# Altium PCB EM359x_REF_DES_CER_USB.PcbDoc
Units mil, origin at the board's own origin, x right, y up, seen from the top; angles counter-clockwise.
Board outline 2000 x 1729.04 mil, 4 copper layers (Top Layer, Gnd Layer 2, Power Layer 3, Bottom Layer), stack 61.6 mil thick; 70 components, 61 nets, 290 pads, 313 vias.
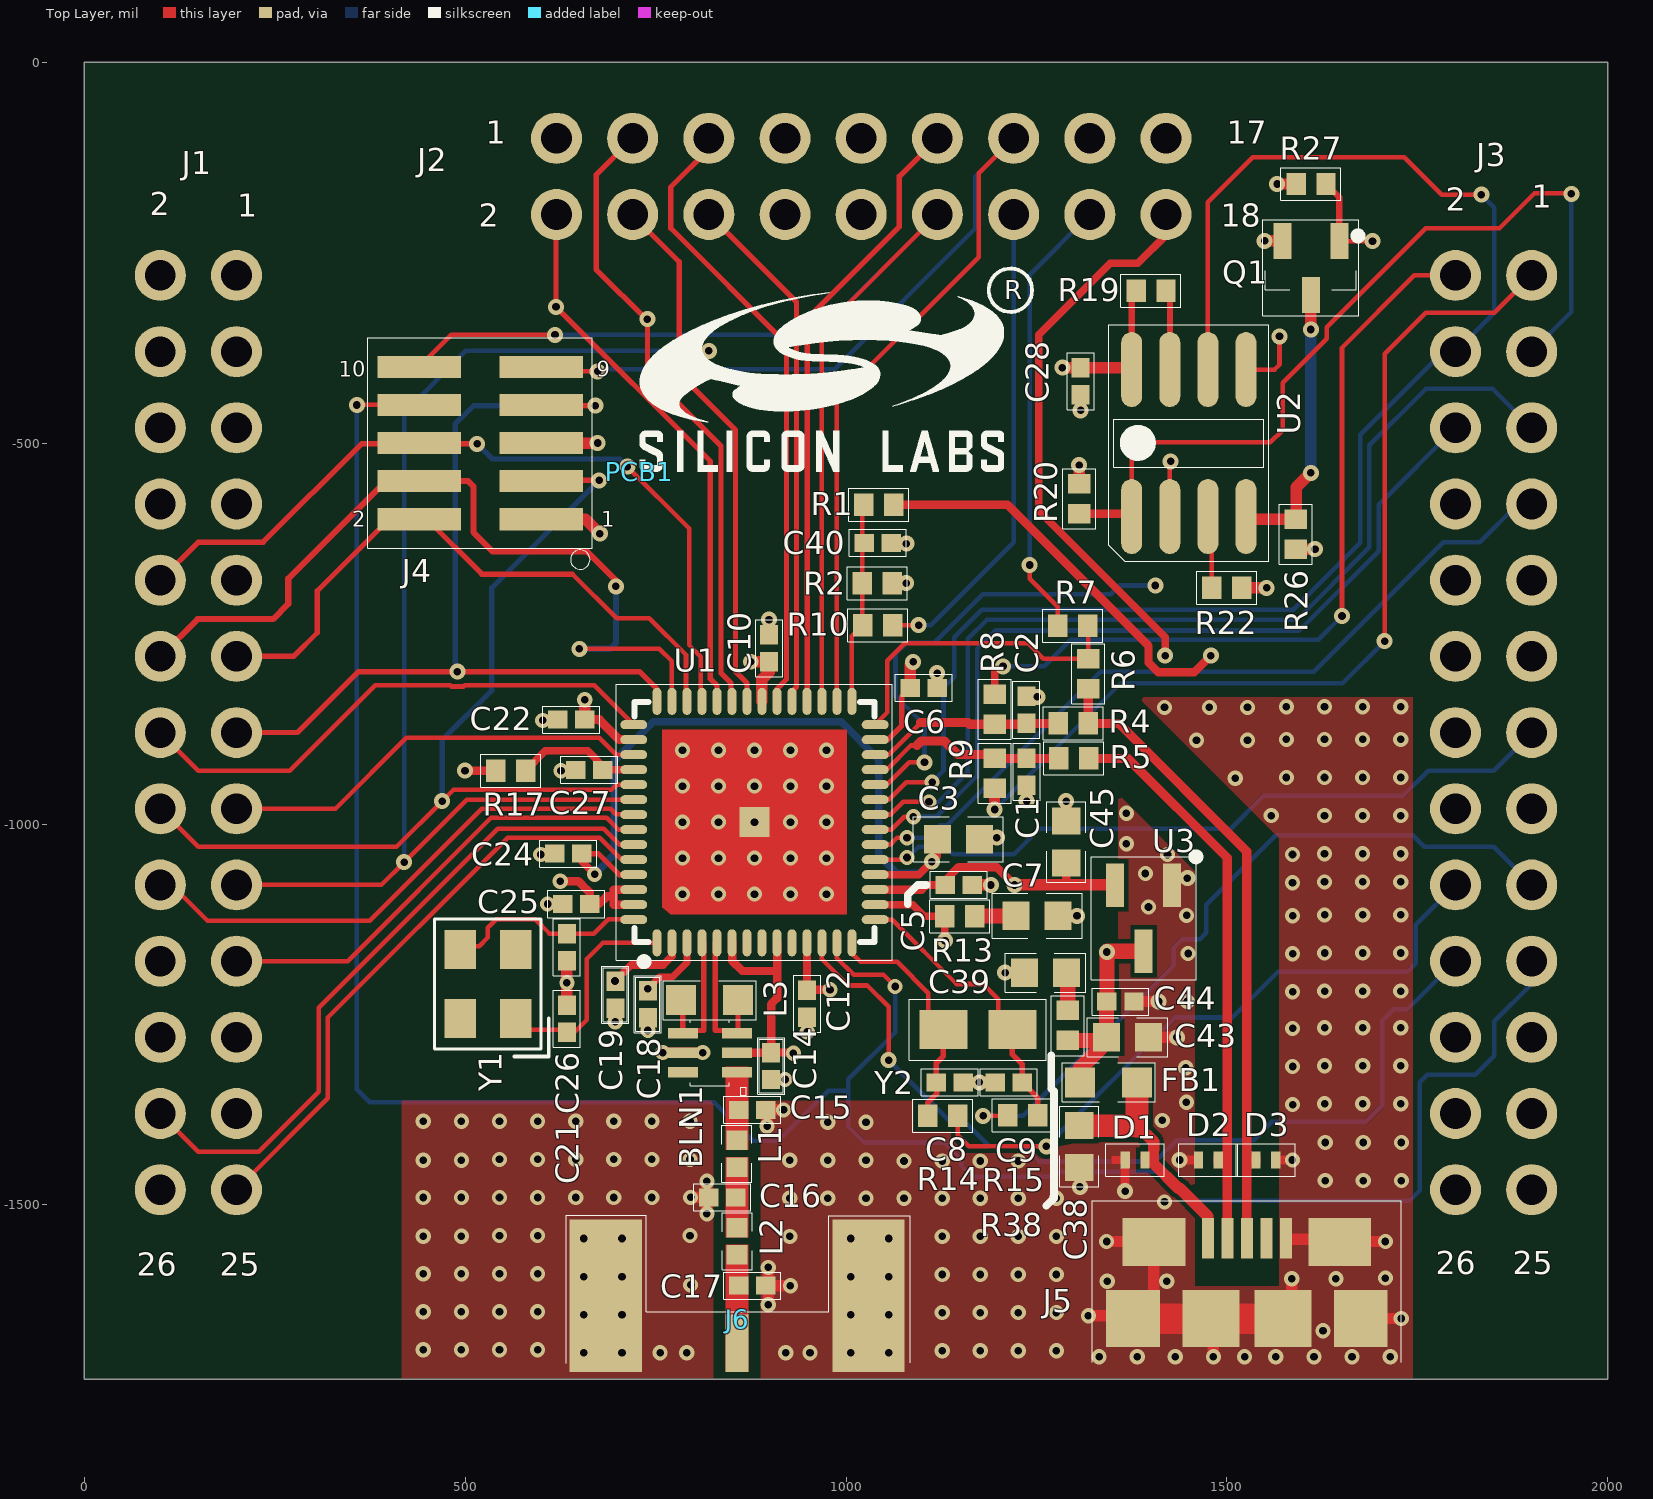
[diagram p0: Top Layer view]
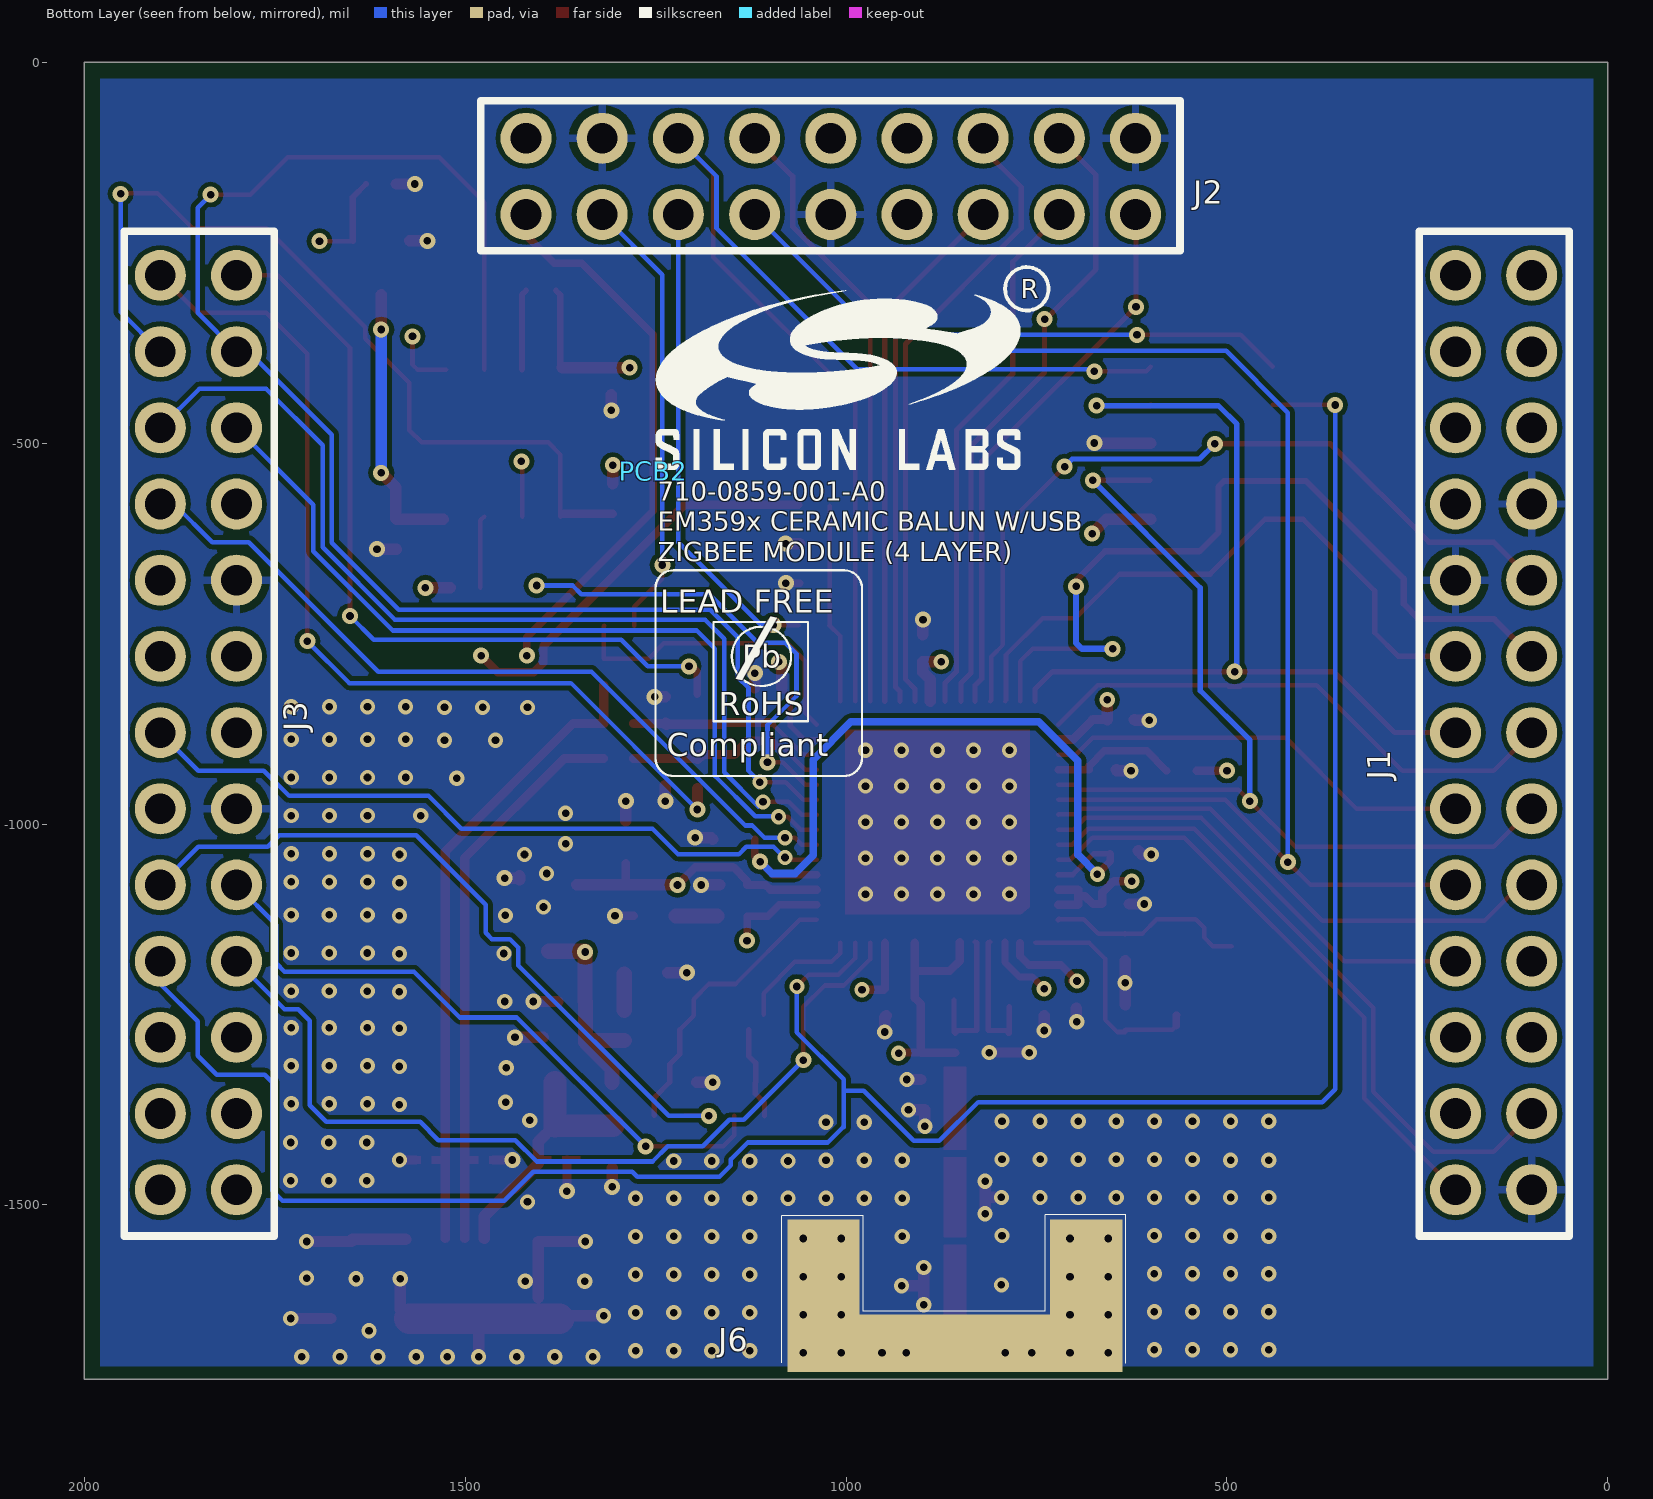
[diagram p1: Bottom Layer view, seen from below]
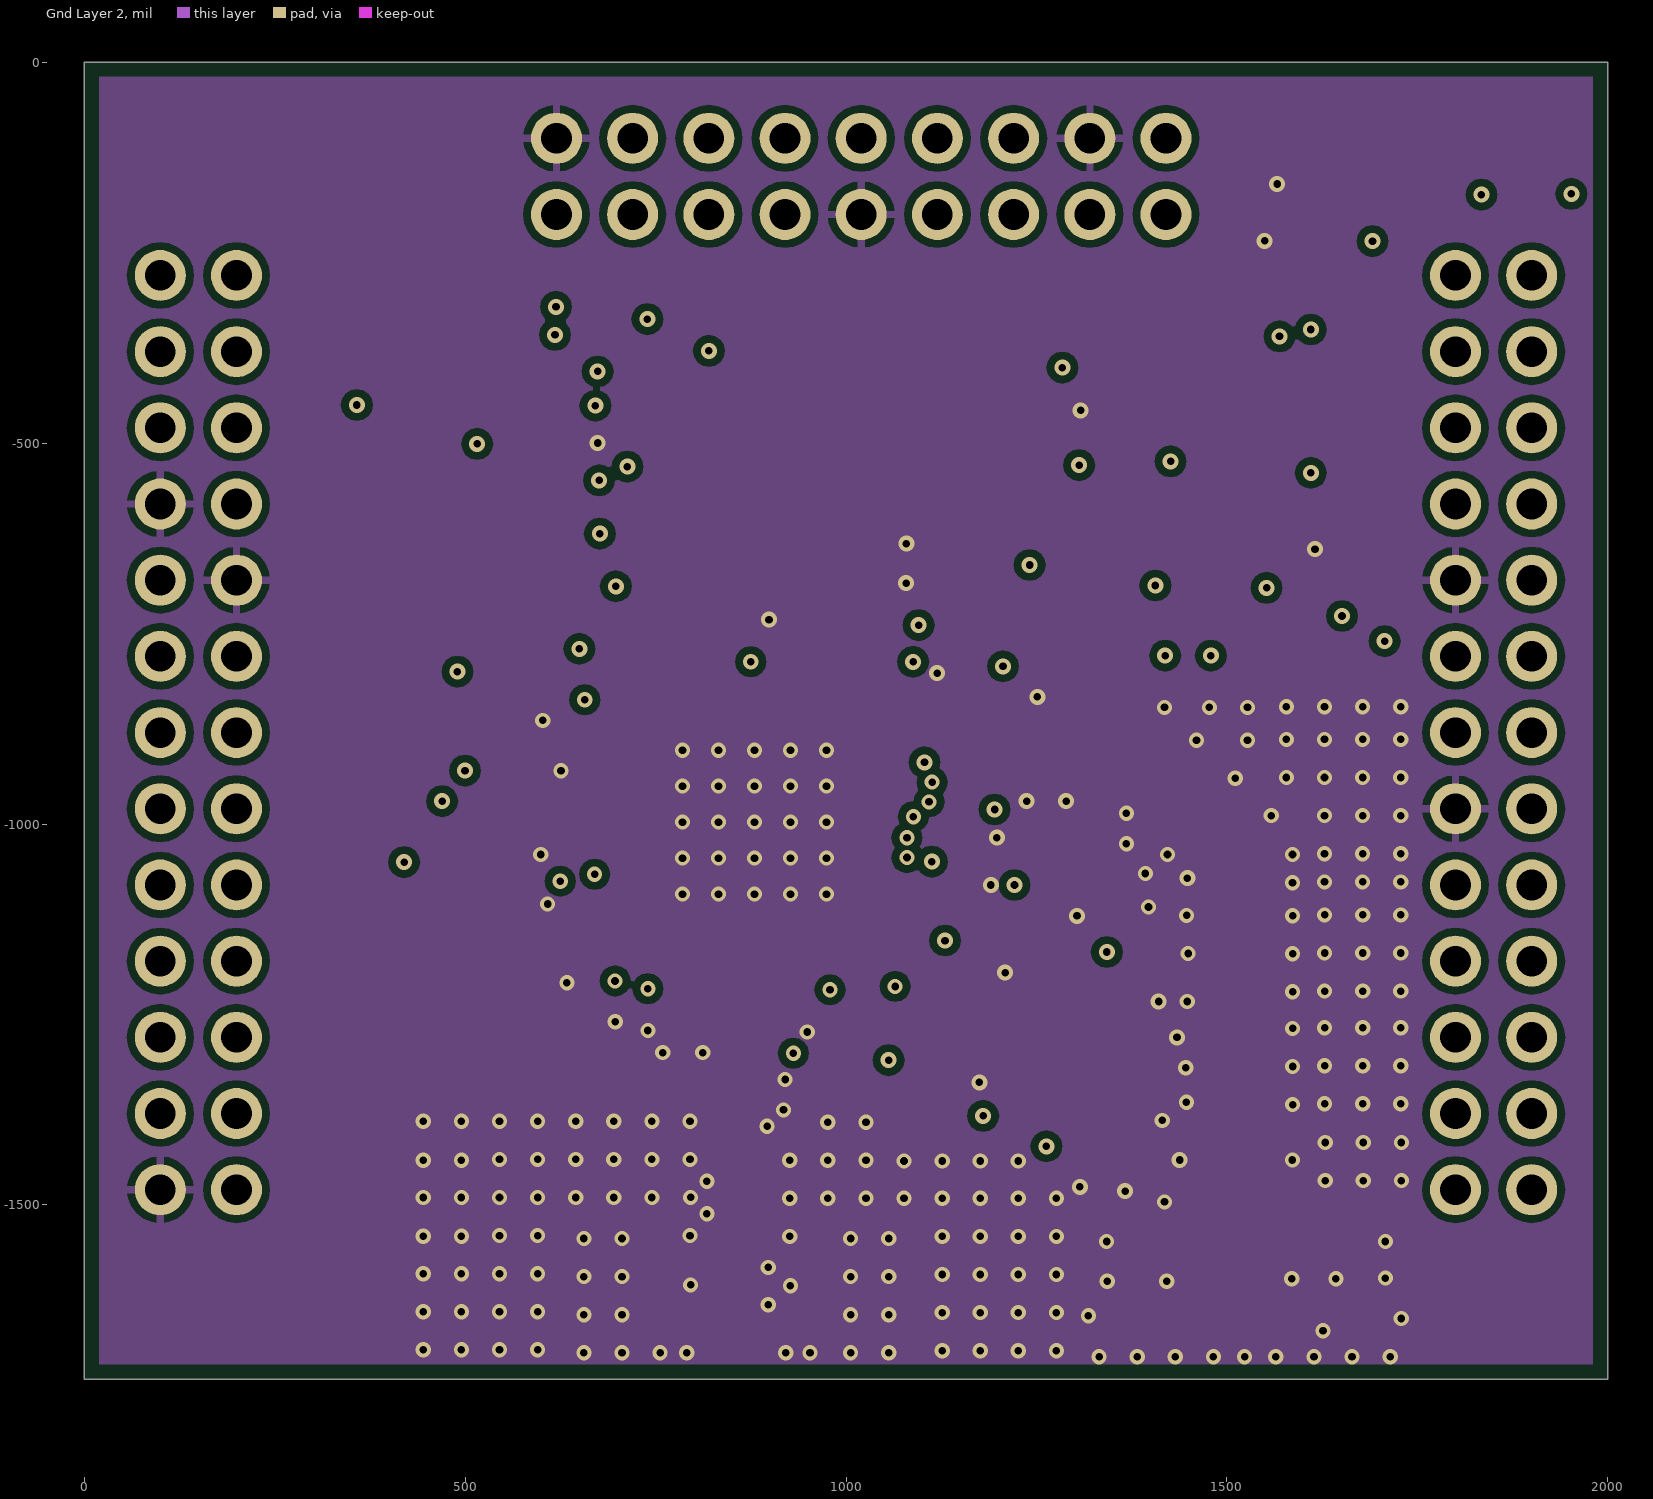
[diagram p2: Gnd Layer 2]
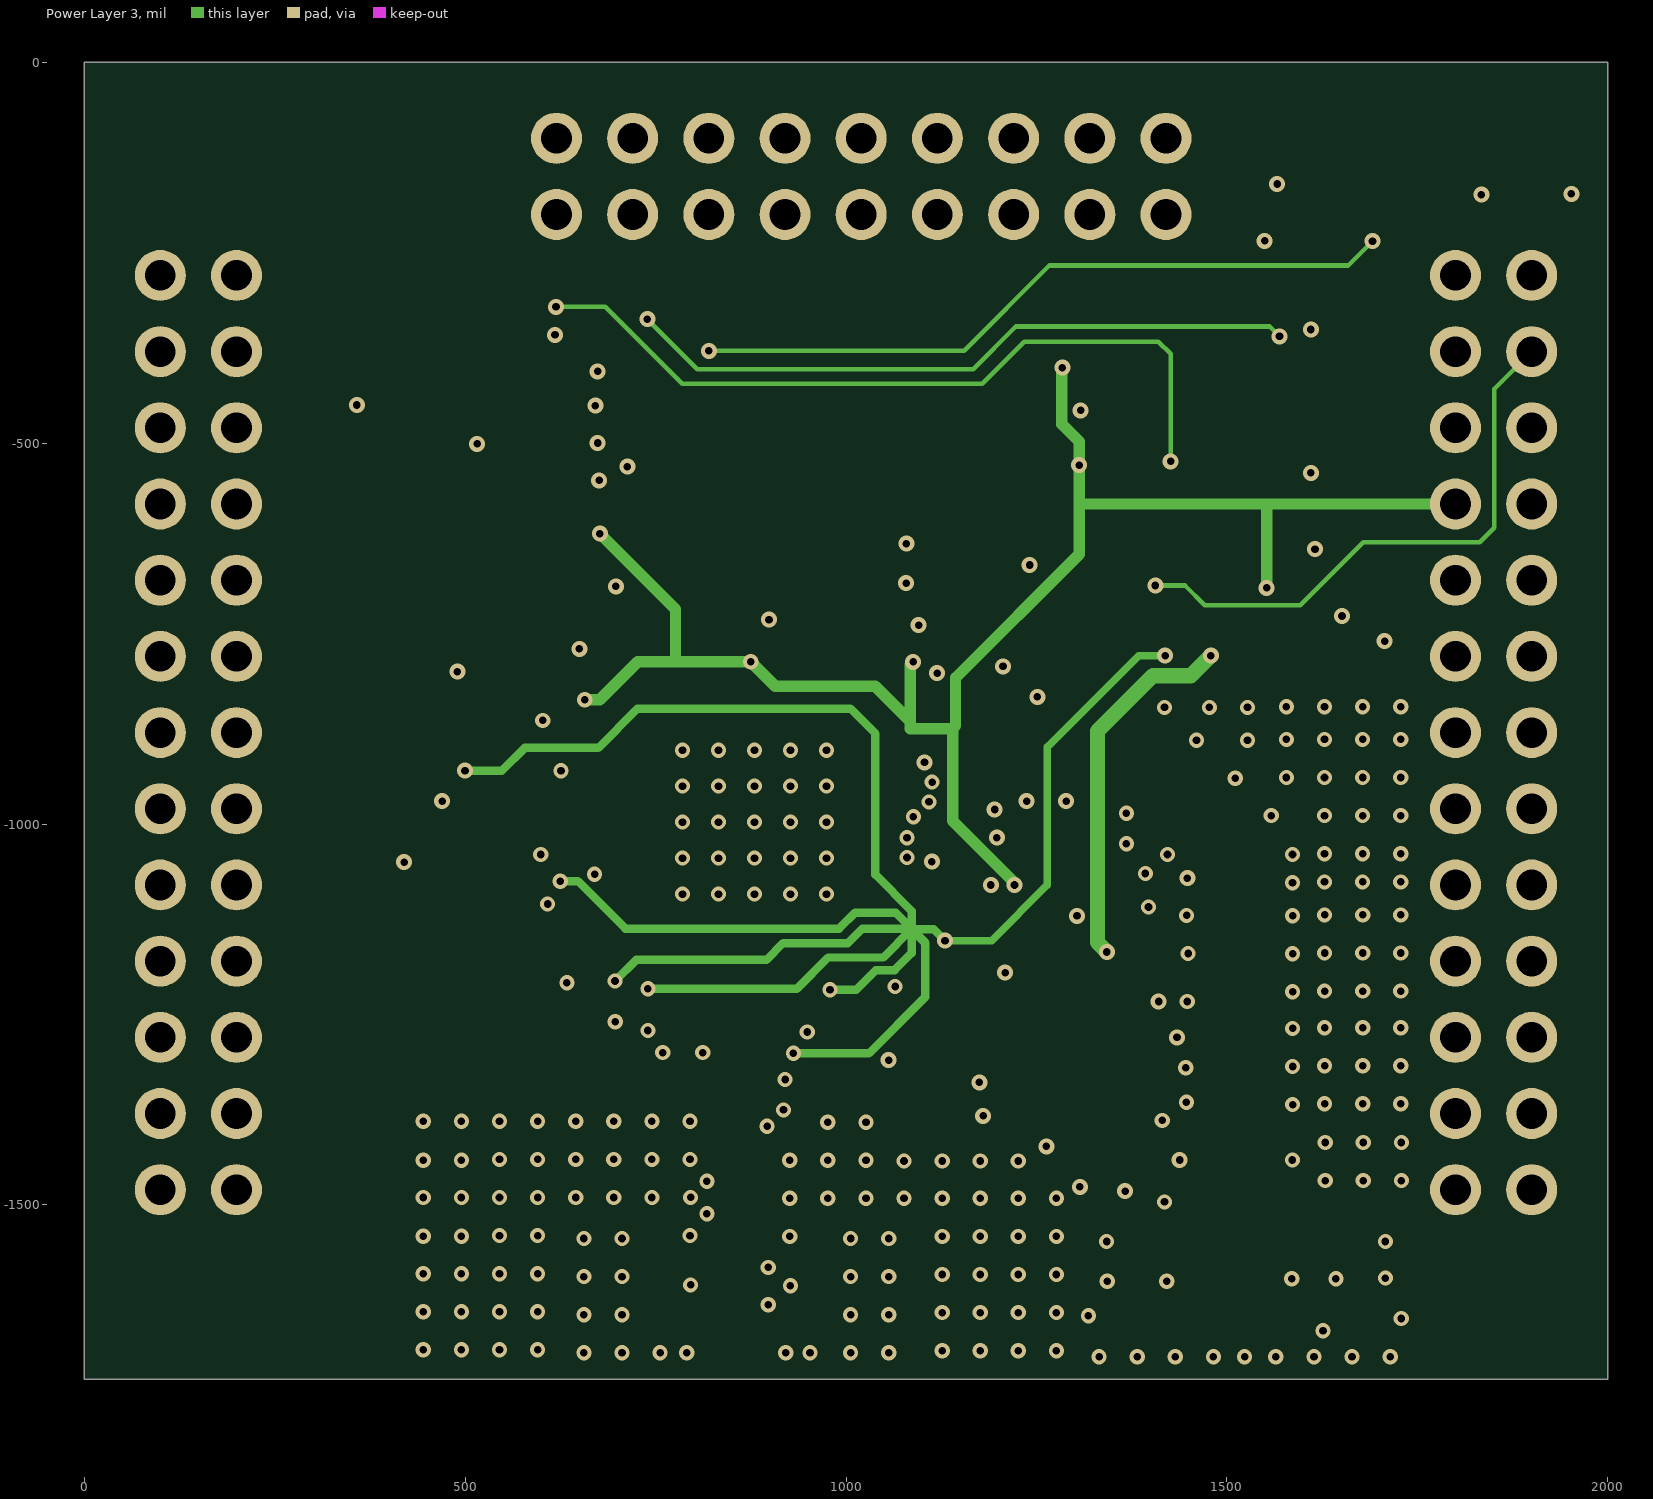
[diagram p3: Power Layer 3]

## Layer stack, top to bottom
Top Solder: solder mask 0.4, Solder Resist, Dk 3.5
Top Layer: signal copper 1.4
Dielectric1: core 16, HR370, Dk 4
Gnd Layer 2: signal copper 1.4
Dielectric2: prepreg 24, HR370, Dk 4
Power Layer 3: signal copper 1.4
Dielectric3: core 16, HR370, Dk 4
Bottom Layer: signal copper 1.4
Bottom Solder: solder mask 0.4, Solder Resist, Dk 3.5

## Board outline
0,-1729.04 0,0 2000,0 2000,-1729

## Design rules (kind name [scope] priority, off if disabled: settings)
Clearance "Stitching GND" [IsStitchingVia and InNet('GND') vs (IsVia and (Not IsStitchingVia)) Or IsPad] p1: gap=50
Clearance Clearance_L2_GND [InNamedPolygon('L2 GND')] p2: gap=10
Clearance [All] p3: gap=6
DiffPairsRouting "Schematic Differential Pairs Routing D_N" [InNet('D_N')] p1: maxlimit=50 minlimit=8 mostfreqgap=9 toplayer_minwidth=15 toplayer_maxwidth=15 toplayer_prefwidth=15 midlayer1_minwidth=15 midlayer1_maxwidth=15 midlayer1_prefwidth=15 midlayer2_minwidth=15 midlayer2_maxwidth=15 midlayer2_prefwidth=15 bottomlayer_minwidth=15 bottomlayer_maxwidth=15 bottomlayer_prefwidth=15 maxuncoupledlength=500
DiffPairsRouting "Schematic Differential Pairs Routing D_P" [InNet('D_P')] p2: maxlimit=50 minlimit=8 mostfreqgap=9 toplayer_minwidth=15 toplayer_maxwidth=15 toplayer_prefwidth=15 midlayer1_minwidth=15 midlayer1_maxwidth=15 midlayer1_prefwidth=15 midlayer2_minwidth=15 midlayer2_maxwidth=15 midlayer2_prefwidth=15 bottomlayer_minwidth=15 bottomlayer_maxwidth=15 bottomlayer_prefwidth=15 maxuncoupledlength=500
DiffPairsRouting "Schematic Differential Pairs Routing PA01_D_N" [InNet('PA01_D_N')] p3: maxlimit=50 minlimit=8 mostfreqgap=9 toplayer_minwidth=15 toplayer_maxwidth=15 toplayer_prefwidth=15 midlayer1_minwidth=15 midlayer1_maxwidth=15 midlayer1_prefwidth=15 midlayer2_minwidth=15 midlayer2_maxwidth=15 midlayer2_prefwidth=15 bottomlayer_minwidth=15 bottomlayer_maxwidth=15 bottomlayer_prefwidth=15 maxuncoupledlength=500
DiffPairsRouting "Schematic Differential Pairs Routing PA01_D_P" [InNet('PA01_D_P')] p4: maxlimit=50 minlimit=8 mostfreqgap=9 toplayer_minwidth=15 toplayer_maxwidth=15 toplayer_prefwidth=15 midlayer1_minwidth=15 midlayer1_maxwidth=15 midlayer1_prefwidth=15 midlayer2_minwidth=15 midlayer2_maxwidth=15 midlayer2_prefwidth=15 bottomlayer_minwidth=15 bottomlayer_maxwidth=15 bottomlayer_prefwidth=15 maxuncoupledlength=500
DiffPairsRouting [All] p5: maxlimit=10 minlimit=10 mostfreqgap=10 toplayer_minwidth=15 toplayer_maxwidth=15 toplayer_prefwidth=15 midlayer1_minwidth=15 midlayer1_maxwidth=15 midlayer1_prefwidth=15 midlayer2_minwidth=15 midlayer2_maxwidth=15 midlayer2_prefwidth=15 bottomlayer_minwidth=15 bottomlayer_maxwidth=15 bottomlayer_prefwidth=15 maxuncoupledlength=500
Height [All] p1 off: minheight=0 maxheight=1000 prefheight=500
HoleSize [All] p1: absolutevalues=TRUE maxlimit=130 minlimit=1 maxpercent=80.000 minpercent=20.000
MatchedLengths "Schematic Matched Net Lengths_3" [InNet('PA01_D_P')] p1: tolerance=100 checknetsindiffpair=TRUE checkdiffpairvsdiffpair=FALSE checkothers=FALSE
MatchedLengths "Schematic Matched Net Lengths_2" [InNet('D_P')] p2: tolerance=100 checknetsindiffpair=TRUE checkdiffpairvsdiffpair=FALSE checkothers=FALSE
MatchedLengths "Schematic Matched Net Lengths_1" [InNet('D_N')] p3: tolerance=100 checknetsindiffpair=TRUE checkdiffpairvsdiffpair=FALSE checkothers=FALSE
MatchedLengths "Schematic Matched Net Lengths" [InNet('PA01_D_N')] p4: tolerance=100 checknetsindiffpair=TRUE checkdiffpairvsdiffpair=FALSE checkothers=FALSE
MatchedLengths MatchedLengths_SW [InNetClass('SW')] p5: tolerance=100 checknetsindiffpair=TRUE checkdiffpairvsdiffpair=TRUE checkothers=TRUE
MatchedLengths MatchedLengths_ETM [InNetClass('ETM')] p6: tolerance=100 checknetsindiffpair=TRUE checkdiffpairvsdiffpair=TRUE checkothers=TRUE
MinimumSolderMaskSliver MinimumSolderMaskSliver_1 [InComponent('U1') vs InComponent('U1')] p1: minsoldermaskwidth=2.5
MinimumSolderMaskSliver [All] p2: minsoldermaskwidth=3.75
PolygonConnect PolygonConnect_Component [All vs InAnyComponent and not InComponent('U1') and not InComponent('J6') and not InComponent('C15') and not InComponent('C16') and not InComponent('C17') and not InComponent('J5') and not InComponent('C38') and not InComponent('D1') and not InComponent('C43') and not InComponent('C44') and not InComponent('U3') and not InComponent('D2') and not InComponent('D3')] p1: connectstyle=Relief reliefconductorwidth=10 reliefentries=4 polygonreliefangle="90 Angle" airgapwidth=10
PolygonConnect [All] p2: connectstyle=Direct reliefconductorwidth=10 reliefentries=4 polygonreliefangle="90 Angle" airgapwidth=10
RoomDefinition 3_SCH0859-001_Main [InComponentClass('3_SCH0859-001_Main')] p1: confinementstyle=ConfineIn formatcopy=TRUE lockcomponents=FALSE outline 11.6,-15.7 14.85,-19.73 1980.1,-19.73 1980.1,-2119.8 16.41,-2119.8 16.41,-19.73
RoutingVias [All] p1: holewidth=10 width=21 viastyle="Through Hole" minholewidth=10 minwidth=19 maxholewidth=28 maxwidth=50
SilkToSilkClearance [All] p1 off: silktosilkclearance=5
SilkToSolderMaskClearance SilkscreenOverComponentPads [IsPad] p1 off: minsilkscreentomaskgap=10 clearancetoexposedcopper=TRUE
SolderMaskExpansion SolderMaskExpansion_Via [IsVia] p1: expansion=-100
SolderMaskExpansion [All] p2: expansion=3
Width "Schematic Width Constraint_3" [InNet('D_N')] p1: maxlimit=60 minlimit=6 preferedwidth=12
Width "Schematic Width Constraint_2" [InNet('D_P')] p2: maxlimit=60 minlimit=6 preferedwidth=12
Width "Schematic Width Constraint_1" [InNet('PA01_D_N')] p3: maxlimit=60 minlimit=6 preferedwidth=12
Width "Schematic Width Constraint" [InNet('PA01_D_P')] p4: maxlimit=60 minlimit=6 preferedwidth=12
Width [All] p5: maxlimit=40 minlimit=6 preferedwidth=6
23 further rules are at their usual default settings.

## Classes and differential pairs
differential pair D: +D_P -D_N
differential pair PA01_D: +PA01_D_P -PA01_D_N

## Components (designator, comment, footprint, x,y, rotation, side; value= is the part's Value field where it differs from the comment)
BLN1 "CHIP MULTILAYER CERAMIC, 2.4 GHZ. 50/100 Ohm" BLN_0805 856.87,-1325.62 r270 top
C1 "33pF" C_0402#1 1237,-949.44 r0 top
C2 "33pF" C_0402#1 1236.72,-832.56 r180 top
C3 "1.0uF" C_0603#1 1120,-1020 r0 top
C5 "0.1uF" C_0402#1 1130,-1080 r270 top
C6 "0.1uF" C_0402#1 1084.3,-821.28 r270 top
C7 "2.2uF" C_0603#1 1223.25,-1120.63 r0 top
C8 "22PF, (DNI)" C_0402#1 1118.56,-1339 r270 top
C9 "33pF, (DNI)" C_0402#1 1231.44,-1339 r90 top
C10 "0.1uF" C_0402#1 899,-787 r0 top
C12 "10NF" C_0402#1 949,-1218 r180 top
C14 "10pF" C_0402#2 901.67,-1317.63 r90 top
C15 "1pF" C_0402#3 859,-1375.22 r270 top
C16 "1.8pF" C_0402#3 855,-1490 r90 top
C17 "1pF" C_0402#3 859,-1606 r270 top
C18 "10NF" C_0402#2 740,-1236.68 r270 top
C19 "10NF" C_0402#2 697.43,-1224.04 r270 top
C21 "6.8pF" C_0402#1 633.72,-1273.01 r0 top
C22 "0.1uF" C_0402#1 657,-863 r90 top
C24 "10NF" C_0402#1 653,-1039 r90 top
C25 "10pF" C_0402#1 663.44,-1105 r90 top
C26 "6.8pF" C_0402#1 633.72,-1143.78 r180 top
C27 "0.47uF" C_0402#1 681,-929 r90 top
C28 "10NF, (DNI)" C_0402#1 1308,-401 r180 top
C38 "1.0uF" C_0603#2 1306,-1395.88 r270 top
C39 "4.7uF" C_0603#2 1289.12,-1195 r180 top
C40 "330pF" C_0402#3 1024,-631 r270 top
C43 "1.0uF, (DNI)" C_0603#2 1342,-1280 r0 top
C44 "10NF, (DNI)" C_0402#3 1342.56,-1233 r270 top
C45 "1.0uF, (DNI)" C_0603#2 1289,-1051.12 r90 top
D1 "TVS" TVS_0402 1379.5,-1441 r0 top
D2 "TVS" TVS_0402 1475.5,-1441 r0 top
D3 "TVS" TVS_0402 1551,-1441 r180 top
FB1 "60Ohm 100MHz" L_0603 1381.8,-1339 r270 top
J1 "HEADER 13 x 2" HEADER-26-SUL-THRU-SHRD 200,-280 r270 bottom locked
J2 "HEADER 9 x 2" HEADER-18-SUL-THRU-SHRD 620,-100 r0 bottom locked
J3 "HEADER 13 x 2" HEADER-26-SUL-THRU-SHRD 1900,-280 r270 bottom locked
J4 "FTSH-105-01-F-DV-K, (DNI)" 610-0019-000 520,-500 r0 top
J5 "10118192-0001LF" FCI_10118192-0001LF 1526,-1544 r0 top
J6 "SMA_JACK_SMD" SMA_WIDE 857,-1729 r180 top
L1 "2.7nH" L_0402 856.9,-1414.9 r270 top
L2 "2.7nH" L_0402 857.2,-1529.96 r270 top
L3 "3.3nH" L_0603 858.18,-1231.22 r270 top
PCB1 "EM359x Ceramic Balun 4 Layer Reference Design w/USB, SMA Connector, Corporate Logo" 710-0859-001 728.54,-537.44 r0 top
PCB2 "Bottom Silk Screen ID and RoHS Text" 710-0859-001_ROHS 1253,-537 r180 bottom
Q1 "2N7002, (DNI)" SOT23-3L 1610,-270 r270 top
R1 "100k" R_0402 1023,-581 r0 top
R2 "150k" R_0402 1021.42,-683.98 r0 top
R4 "33 Ohm" R_0402 1278.63,-868 r0 top
R5 "33 Ohm" R_0402 1279,-914 r0 top
R6 "1.5k" R_0402 1318,-783 r270 top
R7 "DNI" R_0402 1317.37,-740 r180 top
R8 "DNI" R_0402 1195,-829.63 r270 top
R9 "DNI" R_0402 1195,-953.37 r90 top
R10 "DNI" R_0402 1061.42,-738.98 r180 top
R13 "1 Ohm" R_0402 1129.63,-1121 r0 top
R14 "0_OHM" R_0402 1107.07,-1382.99 r0 top
R15 "0_OHM" R_0402 1251.51,-1382.5 r180 top
R17 "10 Ohm" R_0402 540,-930 r0 top
R19 "100K, (DNI)" R_0402 1420,-300 r180 top
R20 "100K, (DNI)" R_0402 1306,-593 r90 top
R22 "100K, (DNI)" R_0402 1480,-690 r0 top
R26 "EMBER_RESISTOR.1" R_0402 1590,-600 r270 top
R27 "100K, (DNI)" R_0402 1630,-160 r180 top
R38 "0.51 ohm" R_0402 1291,-1244.63 r270 top
U1 "EM359x" EM359X 879.84,-997.54 r90 top
U2 "8M (256K x 32), (DNI)" SOIC127P600-8M 1450,-500 r90 top
U3 "LDO, (DNI)" TSOP95P280X90-3N 1390.61,-1123.69 r270 top
Y1 "24MHz" ABM8 530,-1210 r90 top
Y2 "32.768KHz, 12.5pF, (DNI)" IL3X 1173,-1270 r0 top

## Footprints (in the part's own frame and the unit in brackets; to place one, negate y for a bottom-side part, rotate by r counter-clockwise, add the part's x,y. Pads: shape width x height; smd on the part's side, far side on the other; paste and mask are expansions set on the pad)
610-0019-000 [mil]
  rect 110x29 smd: 1(80,-100) 2(-80,-100) 3(80,-50) 4(-80,-50) 5(80,0) 6(-80,0) 7(80,50) 8(-80,50) 9(80,100) 10(-80,100)
  silkscreen extent -148,-166 147,138, body extent -68,-125 68,125, height 225
710-0859-001 [mil] "EM359x Ceramic Balun W/USB W/SMA Connector"
  silkscreen extent 1,1 516,266
710-0859-001_ROHS [mil] "EM359x CERAMIC BALUN W/USB W/SMA Connector"
  silkscreen extent 3,-400 519,268
ABM8 [mil]
  rect 51.18x41.34 smd: 1(-45.28,-36.42) 2(45.28,-36.42) 3(45.28,36.42) 4(-45.28,36.42)
  silkscreen extent -95,-80 85,70, body extent -67,-53 67,53, height 31
BLN_0805 [mm]
  rect 0.35x1 smd: 1(0,0) 2(-0.65,0) 3(-1.3,0) 4(-1.3,-1.8) 5(-0.65,-1.8) 6(0,-1.8)
  silkscreen extent -1.75,-1.55 0.78,0.31
C_0402#1 [mm]
  rect 0.6x0.65 smd: 1(0,0) 2(0,0.9)
  silkscreen extent -0.45,-0.5 0.45,1.4, body extent -0.28,-0.05 0.28,0.97, height 1.02
C_0402#2 [mm]
  rect 0.65x0.6 smd: 1(-0.45,0) 2(0.45,0)
  silkscreen extent -0.95,-0.45 0.95,0.45
C_0402#3 [mm]
  rect 0.6x0.65 smd mask+0.051: 1(0,0) 2(0,0.9)
  silkscreen extent -0.45,-0.5 0.45,1.4, body extent -0.28,-0.05 0.28,0.97, height 1.02
C_0603#1 [mm]
  rect 0.9x0.95 smd: 1(0,0) 2(1.4,0)
  silkscreen extent -0.8,-0.75 2.2,0.75, body extent -0.09,-0.39 1.51,0.39, height 0.89
C_0603#2 [mm]
  rect 0.9x0.95 smd mask+0.051: 1(0,0) 2(1.4,0)
  silkscreen extent -0.64,-0.65 2.04,0.65, body extent -0.09,-0.39 1.51,0.39, height 0.89
EM359X [mm] "QFN, 56-Leads, Body 8.0x8.0mm (max), Pitch 0.50mm, IPC Medium Density"
  oval 0.9x0.3 smd mask+0: 1(-4.025,3.25) 2(-4.025,2.75) 3(-4.025,2.25) 4(-4.025,1.75) 5(-4.025,1.25) 6(-4.025,0.75) 7(-4.025,0.25) 8(-4.025,-0.25) 9(-4.025,-0.75) 10(-4.025,-1.25) 11(-4.025,-1.75) 12(-4.025,-2.25) 13(-4.025,-2.75) 14(-4.025,-3.25) 29(4.025,-3.25) 30(4.025,-2.75) 31(4.025,-2.25) 32(4.025,-1.75) 33(4.025,-1.25) 34(4.025,-0.75) 35(4.025,-0.25) 36(4.025,0.25) 37(4.025,0.75) 38(4.025,1.25) 39(4.025,1.75) 40(4.025,2.25) 41(4.025,2.75) 42(4.025,3.25)
  oval 0.3x0.9 smd mask+0: 15(-3.25,-4.025) 16(-2.75,-4.025) 17(-2.25,-4.025) 18(-1.75,-4.025) 19(-1.25,-4.025) 20(-0.75,-4.025) 21(-0.25,-4.025) 22(0.25,-4.025) 23(0.75,-4.025) 24(1.25,-4.025) 25(1.75,-4.025) 26(2.25,-4.025) 27(2.75,-4.025) 28(3.25,-4.025) 43(3.25,4.025) 44(2.75,4.025) 45(2.25,4.025) 46(1.75,4.025) 47(1.25,4.025) 48(0.75,4.025) 49(0.25,4.025) 50(-0.25,4.025) 51(-0.75,4.025) 52(-1.25,4.025) 53(-1.75,4.025) 54(-2.25,4.025) 55(-2.75,4.025) 56(-3.25,4.025)
  rect 1x1 smd paste-1 mask+0: 57(0,0)
  Top Layer region: -3.08,2.778 -2.844,3.081 3.08,3.08 3.081,-3.076 -3.076,-3.076
  silkscreen extent -4.78,-4.6 4.6,4.6, body extent -4,-4 4,4, height 0.9
FCI_10118192-0001LF [mm] "USB Connector - Surface Mount"
  rect 0.4x1.35 smd mask+0.076: 1(-1.3,0) 2(-0.65,0) 3(0,0) 4(0.65,0) 5(1.3,0)
  rect 2.1x1.6 smd mask+0.076: 6(3.1,-0.125) 11(-3.1,-0.125)
  rect 1.8x1.9 smd mask+0.076: 7(3.8,-2.675) 10(-3.8,-2.675)
  rect 1.9x1.9 smd mask+0.076: 8(1.2,-2.675) 9(-1.2,-2.675)
  silkscreen extent -5.15,-4.13 5.15,1.26, body extent -4.16,-5.69 4.16,0.35, height 3
HEADER-18-SUL-THRU-SHRD [mm]
  round 1.7 hole 1.02: 1(0,0) 2(0,2.54) 3(2.54,0) 4(2.54,2.54) 5(5.08,0) 6(5.08,2.54) 7(7.62,0) 8(7.62,2.54) 9(10.16,0) 10(10.16,2.54) 11(12.7,0) 12(12.7,2.54) 13(15.24,0) 14(15.24,2.54) 15(17.78,0) 16(17.78,2.54) 17(20.32,0) 18(20.32,2.54)
  silkscreen extent -1.48,-1.25 21.83,3.75, body extent -1.5,-1.25 21.82,3.75, height 8.5
HEADER-26-SUL-THRU-SHRD [mm]
  round 1.7 hole 1.02: 1(0,0) 2(0,2.54) 3(2.54,0) 4(2.54,2.54) 5(5.08,0) 6(5.08,2.54) 7(7.62,0) 8(7.62,2.54) 9(10.16,0) 10(10.16,2.54) 11(12.7,0) 12(12.7,2.54) 13(15.24,0) 14(15.24,2.54) 15(17.78,0) 16(17.78,2.54) 17(20.32,0) 18(20.32,2.54) 19(22.86,0) 20(22.86,2.54) 21(25.4,0) 22(25.4,2.54) 23(27.94,0) 24(27.94,2.54) 25(30.48,0) 26(30.48,2.54)
  silkscreen extent -1.48,-1.2 32.02,3.8, body extent -1.5,-1.25 32,3.75, height 8.5
IL3X [mil]
  rect 62.99x51.18 smd: 1(-45.28,0) 2(45.28,0)
  silkscreen extent -90,-40 90,40, body extent -63,-30 63,30, height 36
L_0402 [mm]
  rect 0.65x0.7 smd: 1(0,0) 2(0.9,0)
  silkscreen extent -0.5,-0.5 1.4,0.5, body extent -0.06,-0.28 0.95,0.28, height 1.02
L_0603 [mm]
  rect 1x1 smd: 1(0,0) 2(0,-1.9)
  silkscreen extent -0.65,-2.5 0.65,0.6, body extent -0.39,-1.74 0.39,-0.14, height 0.89
R_0402 [mm]
  rect 0.65x0.75 smd: 1(0,0) 2(1,0)
  silkscreen extent -0.5,-0.55 1.5,0.55, body extent -0.01,-0.28 1,0.28, height 1.02
SMA_WIDE [mil]
  rect 29.67x75 smd: 1(0,-47.5)
  rect 95x200 smd: 2(-172.5,-110) 3(172.5,-110)
  rect 95x200 smd far side: 4(-172.5,-110) 5(172.5,-110)
  rect 250x75 smd far side: 6(0,-47.5)
  silkscreen extent -227,-216 224,-21, body extent -188,-148 188,378, height 161
SOIC127P600-8M [mm] "SOIC, 8-Leads, Body 4.9x3.9mm, Pitch 1.27mm, IPC Low Density"
  oval 2.5x0.7 smd: 1(-2.45,1.905) 2(-2.45,0.635) 3(-2.45,-0.635) 4(-2.45,-1.905) 5(2.45,-1.905) 6(2.45,-0.635) 7(2.45,0.635) 8(2.45,1.905)
  silkscreen extent -3.94,-2.67 3.94,2.67, body extent -2,-2.5 2,2.5, height 1.75
SOT23-3L [mm] "SOT23, 3-Leads, Body 2.9x1.3mm, Pitch 0.95mm, Lead Span 2.5mm, IPC High Density"
  rect 1.2x0.6 smd: 1(-0.9,0.95) 2(-0.9,-0.95) 3(0.9,0)
  silkscreen extent -1.6,-1.6 1.6,1.7, body extent -0.7,-1.5 0.7,1.5, height 1.1
TSOP95P280X90-3N [mm] "SC59, Skyworks TSOP, 3-Leads, Body 2.85x1.53mm, Pitch 0.95mm, IPC Medium Density"
  rect 1.45x0.6 smd: 1(-1.1,0.95) 2(-1.1,-0.95) 3(1.1,0)
  silkscreen extent -2.17,-1.75 2.05,1.87, body extent -0.8,-1.5 0.8,1.5, height 1.5
TVS_0402 [mil] "TVS_DIODE_0402"
  rect 12x22 smd mask+2: 1(-13,0) 2(13,0)
  Top Layer region: 7,-5 31,-5 31,5 7,5
  Top Layer region: -31,-5 -7,-5 -7,5 -31,5
  silkscreen extent -38,-22 38,22, body extent -20,-12 20,12, height 40

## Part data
BLN1: library part 566-0075-000, "Balun 0805"
C1 C2: library part 550-0039-000
C3 C38: library part 550-0033-000
C5 C6 C10 C22: library part 550-0034-000
C7: library part 550-0038-000
C8: library part 550-2201-050-DNI
C9: library part 550-0039-000-DNI
C12 C18 C19 C24: library part 550-0036-000
C14 C25: library part 550-1001-050
C15 C17: library part 550-0040-000
C16: library part 550-1P8A-050
C21 C26: library part 550-6P81-050
C27: library part 550-0037-000
C28: library part 550-0036-000-DNI
C39: library part 550-0041-000
C40: library part 550-0042-000
C43 C45: library part 550-0033-000-DNI
C44: library part 550-0035-000-DNI
D1 D2 D3: library part 545-0062-000
FB1: library part 566-0001-000, "*"
J1 J3: library part 610-7116-000
J2: library part 610-7112-000
J4: library part 610-0045-000-DNI, "CONNECTOR, HEADER, SHROUDED, 10 POSITION, DUAL ROW, VERTICAL, 0.050\""
J5: library part 610-0105-000
J6: library part 610-0093-000
L1 L2: library part 566-2N7W-000, "Design Placeholder"
L3: library part 566-3N3S-000, "Design Placeholder"
PCB1: library part 710-0859-001, "PCB BoM ID and Top Side Silk Screen Identifier"
PCB2: library part 710-0859-001_ROHS, "Bottom Side Silk Screen Identifier"
Q1: library part 545-0047-000-DNI, "MOSFET N-Channel"
R1: library part 555-1045-016
R2: library part 555-150K-016
R4 R5: library part 555-33R1-010
R6: library part 555-1521-016
R7 R8 R9 R10 R26: library part 555-0000-DNI
R13: library part 555-1R05-016
R14 R15: library part 555-0000-000
R17: library part 555-1001-010
R19 R20 R22 R27: library part 555-1045-016-DNI
R38: library part 555-0017-000
U1: library part 540-0359-056, "IC, EM359X, ZIGBEE/802.15.4 RF SOLUTION, ARM CORTEX-M3, 64kB RAM, 512kB FLASH, QFN-56"
U2: library part 510-1032-000-DNI, "IC - MEMORY, IC - MEMORY, SERIAL FLASH, 2M (256K X 8), 2.7 V - 3.6 V, -40C  85C, 8-SOIC (0.154\", 3.90MM WIDTH)"
U3: library part 500-0089-000-DNI
Y1: library part 565-2400-004, "Crystal, 3.2 mm x 2.5 mm x 0.7 mm, ABM8"
Y2: library part 565-3271-001-DNI

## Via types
v1: diameter 20/20/20/20 (per signal layer), hole 10, Top Layer to Bottom Layer, 183 vias
v2: diameter 21, hole 10, Top Layer to Bottom Layer, 68 vias
v3: diameter 20, hole 10, Top Layer to Bottom Layer, 37 vias
v4: diameter 20, hole 10, Top Layer to Bottom Layer, tented bottom, 25 vias

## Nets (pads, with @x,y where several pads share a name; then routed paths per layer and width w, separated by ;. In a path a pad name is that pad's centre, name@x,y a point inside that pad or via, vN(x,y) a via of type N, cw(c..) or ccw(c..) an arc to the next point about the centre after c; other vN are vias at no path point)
1V8: BLN1.2 C12.1 C14.2 C18.1 C19.1 C25.1 J2.18 R13.1 R17.1 U1.2 U1.3 U1.6 U1.9 U1.11 U1.16 U1.54 U1.55 | length 4904.3
  Top Layer w7: v1@929.91,-1299.91 v1(931,-1301)
  Top Layer w9: v1(740,-1216.28) 755.28,-1201 772,-1201 791.42,-1181.58 U1.3@791.42,-1154.84
  Top Layer w10: v1(696.88,-1206.03) 717.91,-1185 760,-1185 771.57,-1173.43 U1.2 ; U1.16 1087.8,-1105.8 1103,-1121 R13.1 1129.63,-1152.63 v2(1130,-1153) ; v2@1419,-780 1419,-755 1253,-589 1253,-358 1347,-264 1383,-264 1420,-227 J2.18
  Top Layer w11: v2(500,-930) R17.1 ; v3(625,-1075) 648.59,-1075 660.09,-1086.5 660.22,-1086.5 663.44,-1089.72 C25.1 676,-1105 686,-1095 695,-1095 ; C19.1 697.64,-1206.12 C19.1@703.02,-1206.12 ; U1.55 695.2,-1105.8 695,-1106 695,-1095 ; U1.54 695.12,-1086.12 695,-1086 695,-1095 ; U1.6@850.47,-1154.84 850.47,-1179.47 864,-1193 909.54,-1193 ; BLN1.2@856.55,-1300.03 C14.2@901.55,-1300.03 ; U1.9@909.53,-1156 909.53,-1228.47 901.67,-1236.33 C14.2 v1@929.91,-1299.91 ; C12.1@948.74,-1216 U1.11 ; C12.1@949,-1216 950.44,-1217.44 v3(979,-1217.44)
  Power Layer 3 w10: v2(1130,-1153) 1191,-1153 1264,-1080 1264,-899 1384,-779 v2(1419,-779)
  Power Layer 3 w11: v2(500,-930) 548.35,-930 578.35,-900 674.92,-900 726.24,-848.69 1005.69,-848.69 1038.46,-881.46 1038.46,-1066.46 1086.24,-1114.23 1086.24,-1137.32 ; v3(625,-1075) 648.08,-1075 710.4,-1137.32 991.08,-1137.32 1012.17,-1116.24 1065.15,-1116.24 1086.24,-1137.32 ; v1(696.88,-1206.03) 724.67,-1178.24 895.63,-1178.24 917.55,-1156.32 1002.42,-1156.32 1021.42,-1137.32 1086.24,-1137.32 ; v1(740,-1216.28) 935.36,-1216.28 976.46,-1175.18 1049.11,-1175.18 1086.24,-1138.05 ; v1(931,-1301) 1030,-1301 1104,-1227 1104,-1155.82 1086.24,-1138.05 ; v3(979,-1217.44) 1013.56,-1217.44 1039.29,-1191.71 1063.92,-1191.71 1086.24,-1169.4 1086.24,-1138.05 ; v2(1130,-1153) 1115.05,-1138.05 1086.24,-1138.05 ; 1086.24,-1138.05 1086.24,-1137.32
1V25_CORE: C3.1 C24.1 U1.18 U1.53 | length 987.7
  Top Layer w7: C24.1 675,-1039 702.43,-1066.43 U1.53 ; v2@1112.56,-1049.53 v2(1112.75,-1049.34)
  Top Layer w10: C24.1 653,-1049 v3(670,-1066) ; U1.18 1095.65,-1066.43 v2@1112.56,-1049.53 ; v2(1112.75,-1049.34) 1120,-1042.09 C3.1
  Bottom Layer w10: v3(670,-1066) 696,-1040 696,-917 747,-866 993.46,-866 1043,-915.54 1043,-1041 1067,-1065 1097.09,-1065 v2(1112.75,-1049.34)
D_N: D2.2 J5.2 R5.2 | length 735.6
  Top Layer w12: R5.2 1370,-914 1500.41,-1044.41 1500.41,-1441 J5.2
D_P: D3.2 J5.3 R4.2 R6.2 | length 835.3
  Top Layer w12: R4.2 R6.2 R6.2@1318,-818.14 ; R4.2@1318.13,-868 1357.94,-868 1526,-1036.06 1526,-1441 J5.3
GND: BLN1.5 C1.1 C2.1 C3.2 C5.2 C6.2 C7.2 C8.2 C9.2 C10.2 C12.2 C14.1 C15.2 C16.2 C17.2 C18.2 C19.2 C21.2 C22.2 C24.2 C25.2 C26.2 C27.2 C28.2 C38.2 C39.2 C40.2 C43.2 C44.2 C45.2 D1.1 D2.1 D3.1 J1.8 J1.9 J1.26 J2.1 J2.10 J2.15 J3.10 J3.16 J4.5 J5.5 J5.6 J5.7 J5.8 J5.9 J5.10 J5.11 J6.2 J6.3 J6.4 J6.5 J6.6 Q1.2 R2.2 R26.2 R27.2 U1.57 U3.1 | length 1758.9
  Top Layer w10: R2.2@1060.92,-683.97 v2(1079,-683.97)
  Top Layer w11: C7.2 v2(1303.25,-1120.63)
  Top Layer w12: v2(1366.36,-1482) D1.1@1366.36,-1441.13 ; v2(1438,-1441) D2.1 ; D3.1@1565,-1441 v1(1585.92,-1441)
  Top Layer w13.5: v1(759.4,-1300.03) v1(811.98,-1300.03)
  Top Layer w15: v3(599.28,-1040) 611.56,-1040 C24.2@616.56,-1035 ; J4.5 v2(674,-500) ; v3(601.88,-864) 620.56,-864 C22.2 ; v3(608.32,-1105) C25.2 ; v3(625.88,-930) 644.56,-930 C27.2 ; C21.2 v3(633.72,-1208.39) C26.2 ; C19.2 697.56,-1241.89 v1@697.56,-1259.47 ; v1(740,-1271) C18.2@740,-1251.72 ; v1(796,-1490.12) C16.2@817.41,-1490.12 ; v1(817.41,-1511.5) C16.2@817.41,-1490.12 ; v1(817.41,-1468.77) C16.2@817.41,-1490.12 ; v1(896.43,-1396.73) 896.43,-1375.22 v1(917.93,-1375.22) ; v1(898,-1631) v1(898,-1582) ; C17.2@899,-1606 v1(927,-1606) ; C10.2 v2(899,-731.88) ; C14.1 v1(920.02,-1335.34) ; C12.2@947.37,-1251.81 C12.2 v3(949,-1273) ; C40.2@1060.44,-632 v2(1079.12,-632) ; C6.2 v2(1119.74,-802) ; C5.2 v2(1190,-1080) ; v2(1175,-1339) C9.2 ; C3.2 1177.12,-1018 v2(1198,-1018) ; v2(1208.87,-1195) C39.2 ; v2(1237,-970) C1.1 ; C2.1@1237.16,-833 v2(1251.08,-833) ; C45.2 v2(1289,-970) ; v2(1307,-1476.13) C38.2@1307,-1452 ; v2(1308,-457) C28.2 ; v1(1318.12,-1645.51) J5.10@1372.59,-1645.51 ; v1(1342,-1548) J5.11@1403.95,-1548 ; C44.2 v2(1410.36,-1233) ; C43.2 v2(1434.36,-1280) ; J5.10@1403.95,-1621.76 J5.11 ; U3.1@1428.49,-1068 1428.01,-1068.48 1428.01,-1073.52 1430.53,-1071 v2(1448,-1071) ; J5.9@1479,-1649.32 J5.9 1482.18,-1652.74 v1(1482.18,-1699.3) ; v2(1549.43,-234.57) Q1.2 ; v2(1566,-160) R27.2 ; J5.8@1573,-1649.32 J5.8 1585,-1637.56 v1(1585,-1597) ; J5.5@1577.53,-1545 J5.6@1648.05,-1545 ; R26.2 v2(1615.63,-639.37) ; J5.6@1648.97,-1548 v1(1708,-1548) ; J5.7@1675.92,-1649 v1(1728.76,-1649)
  Top Layer w40: J5.10 J5.9 ; J5.9@1479,-1649.32 J5.8@1573,-1649.32
  other v1: 1332.18,-1699.3 1382.18,-1699.3 1432.18,-1699.3 1523.18,-1699.3 1564.18,-1699.3 1614.18,-1699.3 1664.18,-1699.3 1714.18,-1699.3 1126.18,-1691.3 1176.18,-1691.3 1226.18,-1691.3 1276.18,-1691.3 445.26,-1690.18 495.26,-1690.18 545.26,-1690.18 595.26,-1690.18 1626,-1665 1126.18,-1641.3 1176.18,-1641.3 1226.18,-1641.3 1276.18,-1641.3 445.26,-1640.18 495.26,-1640.18 545.26,-1640.18 595.26,-1640.18 796,-1604.92 1343,-1600 1421,-1600 1643,-1597 1708,-1596 1126.18,-1591.3 1176.18,-1591.3 1226.18,-1591.3 1276.18,-1591.3 445.26,-1590.18 495.26,-1590.18 545.26,-1590.18 595.26,-1590.18 445.26,-1541.18 495.26,-1541.18 926.18,-1541.3 1126.18,-1541.3 1176.18,-1541.3 1226.18,-1541.3 1276.18,-1541.3 545.26,-1540.18 595.26,-1540.18 795.26,-1540.18 1418,-1496 926.18,-1491.3 976.18,-1491.3 1026.18,-1491.3 1076.18,-1491.3 1126.18,-1491.3 1176.18,-1491.3 1226.18,-1491.3 1276.18,-1491.3 445.26,-1490.18 495.26,-1490.18 545.26,-1490.18 595.26,-1490.18 645.26,-1490.18 695.26,-1490.18 745.26,-1490.18 1629,-1468 1679,-1468 1729,-1468 1076.18,-1442.3 1126.18,-1442.3 1176.18,-1442.3 1226.18,-1442.3 445.26,-1441.18 495.26,-1441.18 926.18,-1441.3 976.18,-1441.3 1026.18,-1441.3 545.26,-1440.18 595.26,-1440.18 645.26,-1440.18 695.26,-1440.18 745.26,-1440.18 795.26,-1440.18 1629,-1418 1679,-1418 1729,-1418 976.18,-1391.3 1026.18,-1391.3 445.26,-1390.18 495.26,-1390.18 545.26,-1390.18 595.26,-1390.18 645.26,-1390.18 695.26,-1390.18 745.26,-1390.18 795.26,-1390.18 1415,-1389 1586.19,-1368.29 1628.18,-1367.3 1678.18,-1367.3 1728.18,-1367.3 1446.78,-1365.2 1446,-1320 1586.19,-1318.29 1628.18,-1317.3 1678.18,-1317.3 1728.18,-1317.3 1586.19,-1268.29 1628.18,-1267.3 1678.18,-1267.3 1728.18,-1267.3 697,-1259.47 1448,-1233 1586.19,-1220.29 1628.18,-1219.3 1678.18,-1219.3 1728.18,-1219.3 1449,-1170 1586.19,-1170.29 1628.18,-1169.3 1678.18,-1169.3 1728.18,-1169.3 1447,-1120 1586.19,-1120.29 1628.18,-1119.3 1678.18,-1119.3 1728.18,-1119.3 1397,-1109 1586.02,-1076.99 1628,-1076 1678,-1076 1728,-1076 1393,-1065 1422,-1040 1586.02,-1039.99 1628,-1039 1678,-1039 1728,-1039 1368,-1026 1558,-989 1628,-989 1678,-989 1728,-989 1368,-986 1511,-940 1578,-939 1628,-939 1678,-939 1728,-939 1460,-890 1527,-890 1578,-889 1628,-889 1678,-889 1728,-889 1418,-847 1477,-847 1527,-847 1578,-846 1628,-846 1678,-846 1728,-846
  other v3: 656,-1694 706,-1694 756,-1694 791,-1694 921,-1694 952.8,-1694 1006,-1694 1056,-1694 656,-1644 706,-1644 1006,-1644 1056,-1644 656,-1594 706,-1594 1006,-1594 1056,-1594 656,-1544 706,-1544 1006,-1544 1056,-1544
  other v4: 785.35,-1092.02 832.6,-1092.02 879.84,-1092.02 927.09,-1092.02 974.33,-1092.02 785.35,-1044.78 832.6,-1044.78 879.84,-1044.78 927.09,-1044.78 974.33,-1044.78 785.35,-997.54 832.6,-997.54 879.84,-997.54 927.09,-997.54 974.33,-997.54 785.35,-950.29 832.6,-950.29 879.84,-950.29 927.09,-950.29 974.33,-950.29 785.35,-903.05 832.6,-903.05 879.84,-903.05 927.09,-903.05 974.33,-903.05
JCLK: J1.10 J4.6 U1.39 | length 1048.2
  Top Layer w6: v2(713,-531) 794,-612 794,-765 809.5,-780.5 809.5,-837.63 U1.39
  Top Layer w7: J1.10 150,-630 235,-630 364,-501 v2(516,-501)
  Bottom Layer w7: v2(516,-501) 536,-521 703,-521 v2(713,-531)
NetBLN1_1: BLN1.1 C15.1 L1.1
NetBLN1_3: BLN1.3 L3.1 U1.5 | length 191.2
  Top Layer w7: U1.5@830.79,-1154.84 828.41,-1155.83 828.41,-1271.03 853.14,-1271.03 856.55,-1274.44 858.18,-1272.81 L3.1
NetBLN1_4: BLN1.4 L3.2 U1.4 | length 181.4
  Top Layer w7: L3.2@785.69,-1239.96 785.68,-1269.97 785.68,-1272.45 785.68,-1274.44 787.06,-1274.44 790.46,-1271.04 813.45,-1271.04 813.45,-1155.83 U1.4@811.1,-1154.84
NetC7_1: C7.1 R13.2 | length 53.9
  Top Layer w20: R13.2@1169.37,-1120.63 C7.1
NetC16_1: C16.1 L1.2 L2.1
NetC17_1: C17.1 J6.1 L2.2
NetC27_1: C27.1 R17.2 U1.46 | length 166.2
  Top Layer w10: R17.2 605.37,-904 661,-904 681,-924 C27.1 681.36,-928.64 U1.46
NetC38_1: C38.1 D1.2 FB1.1 J5.1 | length 319.9
  Top Layer w15: 1381.8,-1396.26 1383.27,-1396.27 1403.76,-1416.97 1403.64,-1441.05 1403.61,-1445.62 1436,-1478 1438,-1478 1474.82,-1514.82 J5.1
  Top Layer w30: C38.1 1381.8,-1396.26 ; 1381.8,-1394.81 FB1.1
NetC39_1: C39.1 R38.1 | length 47.7
  Top Layer w20: R38.1 C39.1@1291,-1196.88
NRESET: J3.19 J4.8 U1.13 | length 3206.3
  Top Layer w6: v2(358,-450) J4.8 ; U1.13 988.11,-1175.99 1010.12,-1198 1049.19,-1198 v3(1064.4,-1213.21)
  Bottom Layer w6: v2(358,-450) 358,-1348 375,-1365 826.69,-1365 877.43,-1415.74 911.26,-1415.74 976.93,-1350.07 1003,-1350.07 ; v3(1064.4,-1213.21) 1064.4,-1273.6 1003,-1335 1003,-1350.07 ; J3.19 1900,-1210 1851,-1259 1851,-1304 1826,-1329 1763,-1329 1753,-1339 1753,-1481 1739.61,-1494.39 1448.39,-1494.39 1410.63,-1456.63 1280.37,-1456.63 1274,-1463 1166,-1463 1151,-1448 1151,-1440.25 1128.75,-1418 1024,-1418 1004,-1398 1003,-1398 1003,-1350.07
NSF_GND: Q1.3 R26.1 U2.4 | length 362.9
  Top Layer w15: U2.4@1528.54,-600 R26.1 ; R26.1@1591,-599 1591,-558 v2(1610,-539) ; v2(1610,-351) Q1.3
  Bottom Layer w15: v2(1610,-539) v2(1610,-351)
NSF_HOLD: R19.1 U2.7 | length 105.6
  Top Layer w8: R19.1 1425,-305 U2.7
NSF_WP: R22.1 U2.3 | length 95.6
  Top Layer w6: U2.3 1480,-601.46 R22.1
OSCA: C21.1 U1.1 Y1.1 | length 300.2
  Top Layer w6: Y1.1@566.72,-1265.01 571.98,-1270.27 633.72,-1270.27 C21.1 644.15,-1273.01 660,-1257.16 660,-1177 681,-1156 U1.1
  Top Layer w10: Y1.1@566.22,-1250.86 566.72,-1250.86 Y1.1@566.72,-1265.01
OSCB: C26.1 U1.56 Y1.3 | length 265.7
  Top Layer w6: Y1.3@493.89,-1160.31 518.69,-1160.31 530,-1149 530,-1136 541,-1125 592,-1125 610.78,-1143.78 C26.1 ; C26.1@633.94,-1144 669,-1144 688,-1125 U1.56@720.89,-1125
  Top Layer w7: C26.1 C26.1@633.94,-1144 ; U1.56@720.89,-1125 U1.56
PA0_EMTM: J3.1 R9.1 | length 1243.8
  Top Layer w6: v2(1707,-760) 1707,-383 1761,-329 1851,-329 J3.1
  Top Layer w14: v2(1195,-981) R9.1
  Bottom Layer w6: v2(1195,-981) 1361,-815 1652,-815 v2(1707,-760)
PA01_D_N: C1.2 R5.1 R9.2 U1.25 | length 265.8
  Top Layer w6: U1.25 1053.36,-928.64 1085,-897 1093,-897
  Top Layer w12: 1093,-897 1099,-891 1129,-891 1147,-909 R9.2@1190,-909 ; R9.2 C1.2 R5.1
  Top Layer w15: R9.2@1190,-909 R9.2
PA01_D_P: C2.2 R4.1 R8.2 U1.26 | length 258.9
  Top Layer w6: U1.26 1055.91,-908.95 1097.87,-867
  Top Layer w12: 1097.87,-867 1160,-867 1162,-869 R8.2 C2.2@1235.72,-869 ; C2.2 R4.1
  Top Layer w15: C2.2@1235.72,-869 C2.2
PA1_EMTM: J3.2 R8.1 | length 1056.2
  Top Layer w6: v2(1651,-727) 1651,-375 1746,-280 J3.2
  Top Layer w10: R8.1 1195,-800 1202,-793 v2(1206,-793)
  Bottom Layer w6: v2(1206,-793) 1260,-793 1295,-758 1620,-758 v2(1651,-727)
PA2: R6.1 R7.1 U1.28 | length 415.1
  Top Layer w6: U1.28 1054.3,-853.59 1054.3,-785.83 1077.13,-763 1239,-763 1259,-783 R6.1 1318,-740.63 R7.1
PA2_EMTM: J2.16 R7.2 | length 588
  Top Layer w6: v2(1241,-660) 1241,-678 1278,-715 R7.2
  Bottom Layer w6: v2(1241,-660) 1241,-279 J2.16
PA3: C40.1 R1.1 R2.1 R10.2 U1.29 | length 261.8
  Top Layer w6: U1.29 1007.8,-753.23 R10.2 ; R10.2@1021.42,-738.35 R2.1 R1.1@1021.42,-582.58
PA3_EMTM: J2.14 R10.1 | length 633.7
  Top Layer w6: R10.1@1061.91,-738.98 v2@1095.91,-738.98
  Bottom Layer w6: v2(1095.42,-738.98) 1111.02,-738.98 1220,-630 J2.14
PA4: J2.13 J4.9 U1.30 | length 1624.2
  Top Layer w6: J4.9 606,-406 v2(674,-406) ; U1.30 988.11,-441.89 1174,-256 1174,-146 J2.13
  Bottom Layer w6: v2(674,-406) 677,-403 985,-403 1170,-218 1170,-150 J2.13
PA5: J2.12 J4.10 U1.31 | length 1464.7
  Top Layer w6: J4.10 482,-358 v2(618,-358) ; U1.31 968.43,-351.57 J2.12
  Bottom Layer w6: v2(618,-358) 962,-358 J2.12
PA6: J2.4 U1.36 | length 700.2
  Top Layer w7: J2.4@720,-201 781,-262 781,-408.94 855,-482.94 855,-800 870,-815 U1.36
PA7: J3.13 U1.19 | length 938
  Top Layer w6: U1.19 v3@1080,-1046.75
  Bottom Layer w6: v3@1080,-1045 1095.16,-1029.84 1130.84,-1029.84 1140.5,-1039.5 1220.5,-1039.5 1254,-1006 1505,-1006 1548,-963 1731,-963 1764,-930 1850,-930 J3.13
  other v3: 1080,-1044
PB0: J1.14 U1.43 | length 711.1
  Top Layer w6: J1.14 150,-930 270,-930 382,-818 480.42,-818 481.92,-819.5 498.08,-819.5 499.58,-818 669.8,-818 U1.43
PB1: J2.3 U1.37 U2.5 | length 1801.4
  Top Layer w6: U2.5 1562.46,-403.54 1569,-397 v2(1569,-360)
  Top Layer w7: J2.3 672,-148 672,-272 739.37,-339.37 739.37,-407.31 836,-503.94 836,-802 849,-815 U1.37@849,-839.07
  Power Layer 3 w6: v2(739.37,-337.37) 805,-403 1167,-403 1223,-347 1556,-347 v2(1569,-360)
PB2: J2.2 U1.38 U2.2 | length 1817
  Top Layer w6: U2.2 1425,-525 v2(1426,-524)
  Top Layer w7: J2.2@619.37,-201.33 v2(619.37,-321.31) 822,-523.94 822,-809.43 830.63,-818.06 U1.38
  Power Layer 3 w6: v2@619.37,-321 684,-321 785,-422 1179,-422 1234,-367 1410,-367 1426,-383 v2(1426,-524)
PB3: J3.4 U1.23 U2.6 | length 2040.2
  Top Layer w6: U1.23 1055.99,-968.01 1079,-945 v3(1113,-945) ; U2.6 1475,-184 1534,-125 1732.9,-125 ; 1732.9,-124.9 1782,-174 v2(1834,-174)
  Bottom Layer w6: v3(1113,-945) 1128,-930 1128,-821.31 1142,-807.31 1142,-755 1178,-719 1587,-719 1675,-631 1675,-489 1784,-380 J3.4 1851,-329 1851,-191 v2(1834,-174)
PB4: J3.3 R20.1 U1.24 U2.1 | length 2503.1
  Top Layer w6: U1.24 1053.68,-948.32 1083,-919 v2(1103,-919) ; U2.1 1375,-515 1391,-499 1557,-499 1573,-483 1573,-421 1631,-363 1631,-348 1761,-218 1857.7,-218 1903.7,-172 1951,-172 v2(1952,-173)
  Top Layer w11: R20.1 U2.1@1371.54,-593
  Power Layer 3 w6: v2(1406,-687) 1445,-687 1471,-713 1596,-713 1679,-630 1832,-630 1851,-611 1851,-429 J3.3
  Bottom Layer w6: v2@1103,-919.5 1103,-870 1065,-832 1065,-776.53 1079.53,-762 1116,-762 1179.72,-698.28 1347.72,-698.28 1359,-687 v2(1406,-687) ; J3.3 1952,-328 v2(1952,-173)
PB5: J1.25 U1.52 | length 786.7
  Top Layer w6: J1.25 320,-1360 320,-1254 556,-1018 677,-1018 705.75,-1046.75 U1.52
PB6: J1.24 U1.51 | length 891
  Top Layer w6: J1.24 150,-1430 229.21,-1430 308,-1351.21 308,-1241 543,-1006 682,-1006 703.06,-1027.06 U1.51
PB7: J1.17 Q1.1 R27.1 U1.48 | length 2646.9
  Top Layer w6: J1.17 390,-1080 v2(420,-1050) 502,-968 U1.48 ; Q1.1@1647.83,-235 v2(1691,-235)
  Top Layer w8: R27.1 1647.4,-177.4 Q1.1
  Power Layer 3 w6: v2(820,-379) 1155,-379 1267,-267 1659,-267 v2(1691,-235)
  Bottom Layer w6: v2(420,-1050) 420,-460 501,-379 v2(820,-379)
PC0: J1.16 J4.3 U1.47 | length 1257.2
  Top Layer w6: J1.16 150,-1030 410,-1030 v2(470,-970) 484.87,-955.13 692.27,-955.13 699.08,-948.32 U1.47
  Top Layer w7: J4.3@601,-549 v2(676,-549)
  Bottom Layer w7: v2(470,-970) 470,-890 535,-825 535,-690 v2(676,-549)
PC1: J1.15 U1.45 | length 569
  Top Layer w6: J1.15 330,-980 423,-887 676.33,-887 698.29,-908.95 U1.45
PC2: J1.11 J4.2 U1.40 | length 832.1
  Top Layer w6: 641,-672 699,-730 742,-730 790,-778 790,-837.81 U1.40
  Top Layer w7: J1.11 275,-780 306,-749 306,-694 400,-600 J4.2 450,-600 522,-672 641,-672
PC3: J1.12 J4.4 U1.41 | length 1116.1
  Top Layer w6: v2(650,-770) 755,-770 771.57,-786.57 U1.41
  Top Layer w8: J1.12 149,-731 248,-731 268,-711 268,-678 396,-550 J4.4 504,-550 511,-557 511,-617 536,-642 660,-642 698,-680 v2(698,-688)
  Bottom Layer w8: v2(650,-770) 690.5,-770 698,-762.5 v2(698,-688)
PC4: J1.13 J4.7 U1.42 | length 1202.3
  Top Layer w7: J1.13 280,-880 360,-800 v2(490,-800) 729,-800 751.89,-822.89 U1.42 ; J4.7 601,-451 v2(671,-451)
  Bottom Layer w7: v2(490,-800) 487,-797 487,-475 511,-451 v2(671,-451)
PC5: J3.20 U1.12 | length 1192
  Top Layer w6: U1.12 968.43,-1177.43 1002.98,-1211.98 1027.98,-1211.98 1056,-1240 v2(1056,-1310)
  Bottom Layer w6: v2(1056,-1310) 1134.38,-1388.38 1153.38,-1388.38 1188,-1423 1234,-1423 1254,-1443 1406,-1443 1434,-1415 1535,-1415 1559,-1391 1682,-1391 1704,-1369 1704,-1258 1719,-1243 1737,-1243 J3.20 J3.20@1786,-1180
PC6: C8.1 R14.1 U1.14 Y2.1 | length 285.4
  Top Layer w6: U1.14 1007.8,-1169.8 1019,-1181 1067.08,-1181 1108.12,-1222.04 Y2.1@1108.12,-1250.4
  Top Layer w7: R14.1 1107.07,-1365.93 1119,-1354 C8.1@1119,-1339.44 ; C8.1 1118.56,-1313.44 1127.72,-1304.28 Y2.1
PC6_EMTM: J3.18 R14.2 | length 856.9
  Top Layer w6: R14.2@1146.57,-1382.99 1146.57,-1408.57 1161,-1423 v2(1263,-1423)
  Bottom Layer w6: v2(1263,-1423) 1432,-1254 1507,-1254 1567,-1194 1737,-1194 1748,-1183 1748,-1132 J3.18
PC7: C9.1 R15.1 U1.15 Y2.2 | length 378.8
  Top Layer w6: U1.15 1060.49,-1125.49 1145,-1210 1180,-1210 1200,-1230 1200,-1251.72 Y2.2
  Top Layer w7: Y2.2 1218.28,-1302.28 1231.44,-1315.44 C9.1 1251.51,-1359.07 R15.1
PC7_EMTM: J3.17 R15.2 | length 966.3
  Top Layer w6: v2(1180,-1383) R15.2@1211.64,-1383
  Bottom Layer w6: v2(1180,-1383) 1232.71,-1383 1430,-1185.71 1430,-1162.13 1441.13,-1151 1464.71,-1151 1473,-1142.71 1473,-1106 1564,-1015 1744,-1015 1759,-1030 1850,-1030 J3.17
PD1: J3.7 U1.20 | length 1046.9
  Top Layer w6: U1.20 1057.94,-1027.06 1067,-1018 v3(1080,-1018)
  Bottom Layer w6: v3(1080,-1018) 1080.16,-1017.84 1107,-1017.84 1122.84,-1002 1132,-1002 1334,-800 1614,-800 1784,-630 1832,-630 1882,-580 J3.7
PD2: J3.6 U1.21 | length 1113.7
  Top Layer w6: U1.21 1059.62,-1007.38 1076.53,-990.47 v3(1088.5,-990.47)
  Bottom Layer w6: v3(1088.5,-990.47) 1088.98,-990 1118.97,-990 1172,-936.97 1172,-770 1196,-746 1595,-746 1699,-642 1699,-581 J3.6
PD3: J3.5 U1.22 | length 1291.7
  Top Layer w6: U1.22 1058.31,-987.69 1075,-971 v3(1109,-971)
  Bottom Layer w6: v3@1115,-977 1160,-932 1160,-757 1185,-732 1592,-732 1687,-637 1687,-503 1761,-429 1849,-429 J3.5
PD4: J2.11 U1.32 | length 810
  Top Layer w7: U1.32 949,-838.81 949,-337 1070,-216 1070,-150 J2.11
PE0: J2.6 U1.33 | length 689.2
  Top Layer w7: J2.6 935,-315 935,-820 929.06,-825.94 U1.33
PE1: J2.5 U1.34 | length 828
  Top Layer w7: J2.5 820,-114.07 770,-164.07 770,-218 922,-370 922,-810 909.37,-822.63 U1.34
PE2: J1.18 U1.49 | length 704.9
  Top Layer w6: J1.18 115,-1080 162,-1127 375,-1127 522,-980 691,-980 698,-987 720.68,-987 U1.49
PE3: J1.19 U1.50 | length 605.6
  Top Layer w6: J1.19 346,-1180 534,-992 686,-992 701.38,-1007.38 U1.50
VBRD: C5.1 C6.1 C10.1 C22.1 C28.1 C45.1 J3.8 J4.1 R19.2 R20.2 R22.2 U1.17 U1.27 U1.35 U1.44 U2.8 U3.2 | length 3247.1
  Top Layer w7: U1.27 1055.19,-889.27 1073.04,-871.41 1073.04,-832.53 C6.1
  Top Layer w8: U2.8 1375,-305.63 R19.2
  Top Layer w11: U1.17 1099.3,-1086.12 1105.42,-1080 C5.1 1130,-1074.57 1147.88,-1056.69 1197.8,-1056.69 v2(1221.11,-1080) ; 1289,-1080 C45.1
  Top Layer w12: C22.1 676.08,-863 702.34,-889.27 U1.44
  Top Layer w15: J4.1 658.06,-600 v2(677,-618.94) ; C22.1 v3(657,-837) ; v3(875,-787) C10.1 899,-800.68 889.68,-809.99 U1.35 ; C6.1 1084.3,-790.83 v2(1088.04,-787.09) ; v2(1221.11,-1080) 1289,-1080 U3.2@1353.21,-1080 ; v2(1284,-401) C28.1 U2.8@1372.46,-401 ; R20.2 v2(1306,-529) ; R22.2 v2(1552,-690)
  Power Layer 3 w15: v3(657,-837) 676.68,-837 726.68,-787 776.25,-787 ; v2(677,-618.94) 776.25,-718.19 776.25,-787 ; v2(1088.04,-787.09) 1084.3,-790.83 1084.3,-865.28 ; v2(1221.11,-1080) 1221.11,-1077.17 1140.04,-996.1 1140.04,-875.09 ; v2@1283.34,-399.62 1283.34,-475.34 1306,-498 v2(1306,-529) 1306,-580 ; v2(1552,-690) 1552,-583 ; J3.8 1306,-580 ; 776.25,-787 v3(875,-787) 907.28,-819.28 1038.3,-819.28 1084.3,-865.28 ; 1084.3,-865.28 1084.3,-875.09 1140.04,-875.09 ; 1140.04,-875.09 1143.74,-871.39 1143.74,-808.26 1306,-646 1306,-580
VBUS: C43.1 C44.1 FB1.2 R1.2 R38.2 U3.3 | length 1295.8
  Top Layer w11: R1.2 1212,-581 1397,-766 1397,-788.11 1409.89,-801 1456.86,-801 v2(1478.86,-779)
  Top Layer w20: R38.2 C43.1@1338,-1284 ; FB1.2 1307,-1321 1342,-1286 C43.1 C44.1@1342,-1233.56 ; C44.1 1342.56,-1167.44 1343,-1167 U3.3
  Power Layer 3 w20: v2(1342.36,-1168) 1330,-1155.64 1330,-878 1403,-805 1407.52,-805 1408.02,-805.5 1452.36,-805.5 v2(1478.86,-779)
pads on no net: BLN1.6 J1.1 J1.2 J1.3 J1.4 J1.5 J1.6 J1.7 J1.20 J1.21 J1.22 J1.23 J2.7 J2.8 J2.9 J2.17 J3.9 J3.11 J3.12 J3.14 J3.15 J3.21 J3.22 J3.23 J3.24 J3.25 J3.26 J5.4 U1.7 U1.8 U1.10 Y1.2 Y1.4

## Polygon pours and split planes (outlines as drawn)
GND on Gnd Layer 2 "L2 GND" (solid, remove dead copper, pour order 6): 20.1,-1708.94 1980.1,-1708.94 1980.1,-18.94 20.1,-18.94
GND on Bottom Layer "Bottom GND" (solid, remove dead copper, pour order 5): 19,-1712 1979,-1712 1979,-22 19,-22
GND on Top Layer "Top Layer-GND" (solid, pour order 4): 1743.55,-833.62 1743.55,-1727.66 416.66,-1727.66 416.66,-1363.5 1357.34,-1363.5 1357.34,-833.62

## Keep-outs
Keep-Out Layer:
  text ".Layer_Name" at 5814.2,-4299.1 h70

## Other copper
Top Layer:
  pour cut-out: 1388.09,-838.24 1568.4,-1018.55 1568.4,-1606.57 1458.05,-1606.57 1458.05,-1061.96 1361.96,-965.87
  pour cut-out: 825.8,-1363.5 888.1,-1363.5 888.1,-1727.66 825.8,-1727.66
  region net NetC17_1: 871.79,-1552.48 871.79,-1718.99 842.12,-1718.99 842.12,-1552.48
  region net NetC16_1: 871.79,-1437.67 871.79,-1542.58 842.12,-1542.58 842.12,-1437.67
  region net NetBLN1_1: 871.79,-1427.84 871.79,-1318.77 842.12,-1318.77 842.12,-1427.84
  text ".Layer_Name" at 5814.2,-4299.1 h70
Gnd Layer 2:
  text ".Layer_Name" at 5814.2,-4299.1 h60
Power Layer 3:
  text ".Layer_Name" at 5814.2,-4299.1 h60
Bottom Layer:
  text ".Layer_Name" at 5814.2,-4299.1 h70

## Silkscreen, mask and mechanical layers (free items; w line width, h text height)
Top Overlay:
  lines w10: 1081,-1105 1081,-1093 1094,-1080 1105.42,-1080 ; 1263,-1501 1273,-1491 1273,-1351 1269.35,-1347.35 1269.35,-1303.88
  text "1" at 527,-107 h30
  text "17" at 1500,-107 h30
  text "J3" at 1827,-137 h30
  text "J2" at 437,-143 h30
  text "J1" at 128,-147 h30
  text "1" at 1900,-191 h30
  text "2" at 1787,-195 h30
  text "2" at 86,-201 h30
  text "1" at 201,-203.3 h30
  text "2" at 518,-216 h30
  text "18" at 1492,-216 h30
  text "26" at 1774,-1591 h30
  text "25" at 1875,-1591 h30
  text "26" at 69,-1593 h30
  text "25" at 178,-1593 h30
  text ".Layer_Name" at 5814.2,-4299.1 h70
Bottom Overlay:
  text ".Layer_Name" at 5814.2,-4299.1 h70
Top Paste:
  text ".Layer_Name" at 5814.2,-4299.1 h70
Bottom Paste:
  text ".Layer_Name" at 5814.2,-4299.1 h70
Top Solder:
  text ".Layer_Name" at 5814.2,-4299.1 h70
Bottom Solder:
  text ".Layer_Name" at 5814.2,-4299.1 h70
Drill Guide:
  text ".Layer_Name" at 5814.2,-4299.1 h70
M1 Top Assembly:
  text "J4" at 500,-517 h30
  text "C40" at 1019,-640 h30
  text "U1" at 865,-1007 h30
  text "C45" at 1299,-1045 h30 r90
  text "U3" at 1376,-1132 h30
  text "C39" at 1239,-1203 h30
  text "Y1" at 515,-1222 h30
  text "L3" at 807,-1242 h30
  text "C44" at 1340.56,-1244 h30
  text "Y2" at 1159,-1277 h30
  text "R38" at 1302,-1284.13 h30 r90
  text "C43" at 1342,-1286 h30
  text "BLN1" at 831.67,-1329.16 h30 r90
  text "FB1" at 1324,-1350 h30
  text "C15" at 853,-1385 h30
  text "D1" at 1366,-1411 h30
  text "D2" at 1456,-1414 h30
  text "D3" at 1535,-1415 h30
  text "L1" at 867,-1444 h30 r90
  text "C38" at 1317,-1447 h30 r90
  text "C16" at 817,-1501 h30
  text "L2" at 865,-1559 h30 r90
  text "J5" at 1513,-1605 h30
  text "C17" at 852,-1614 h30
  text "J6" at 842,-1773 h30
  text ".Layer_Name" at 5814.2,-4299.1 h70
M2 Bottom Assembly:
  text "J2" at 1044,-160 h30
  text "J3" at 1875,-844 h30
  text "J1" at 173,-846 h30
  text "J6" at 896.98,-1778 h30
  text ".Layer_Name" at 5814.2,-4299.1 h70
M7 Board Outline:
  the board outline again, w5
M13 Top 3D:
  text ".Layer_Name" at 5814.2,-4299.1 h70
M16 Sheet Border:
  drawing of 3172 lines, arcs and shapes, not listed
  text "1" at 631.84,2787.6 h70
  text "2" at 2989.85,2787.6 h70
  text "3" at 5366.5,2787.6 h70
  text "4" at 7741.85,2787.6 h70
  text "A" at 8829.5,1897.6 h70
  text "B" at 8829.5,21.6 h70
  text "C" at -465.5,-1854.4 h70
  text "C" at 8829.5,-1854.4 h70
  text "TITLE:" at 5809.5,-3277.4 h45
  text ".Title" at 5809.5,-3397.4 h70
  text "FILE NAME:" at 5809.5,-3577.4 h45
  text ".Pcb_File_Name_No_Path" at 5809.5,-3697.4 h70
  text "D" at -465.5,-3726.4 h70
  text "D" at 8829.5,-3726.4 h70
  text ".Company Design Group" at 537.6,-3780.1 h70
  text "Board NO.:" at 5809.5,-3877.4 h45
  text "REV:" at 7909.5,-3877.4 h45
  text ".Company Address 1" at 4554.5,-3897.4 h70
  text "The information in this document is subject to change without notice. The statements, configurations," at -245.5,-3977.4 h45
  text ".Company Address 2" at 4554.5,-3997.4 h70
  text ".Board No" at 5809.5,-3997.4 h70
  text ".Board Rev" at 7909.5,-3997.4 h70
  text "technical data and recommendations in this  document are believed to be accurate and reliable, but are" at -245.5,-4052.4 h45
  text ".Company Address 3" at 4554.5,-4097.4 h70
  text "presented without express or implied warranty. The information in this document is  the proprietary and" at -245.5,-4127.4 h45
  text "Layer:" at 5809.5,-4177.4 h45
  text "DATE:" at 7909.5,-4177.4 h45
  text ".Company Web Site" at 4554.5,-4197.4 h70
  text "confidential property of Ember Corporation and is priviliged. No part of the drawing or information may" at -245.5,-4202.4 h45
  text "be duplicated or otherwise  used without the express permission of Ember Corporation" at -245.5,-4277.4 h45
  text ".Company Tel" at 4554.5,-4297.4 h70
  text ".Print_Date" at 7909.5,-4297.4 h70
  text "1" at 631.84,-4512.4 h70
  text "2" at 2989.85,-4512.4 h70
  text "3" at 5366.5,-4512.4 h70
  text "4" at 7741.85,-4512.4 h70
Drill Drawing:
  drawing of 349 lines, arcs and shapes, not listed
  text "Fabrication Notes:" at 130.2,2444 h70
  text "1. All dimensions in inches.  Tolerance = +/- 0.005\" unless noted otherwise" at 130.2,2344 h45
  text "2. All materials: laminates, resins, metallizations and soldermask to be compliant to EU RoHS directive 2002/95/EC IAW SP-12509-01." at 130.2,2269 h45
  text "3. 370 HR FR-4 or similar grade glass epoxy." at 130.2,2194 h45
  text "4. Tg > 170 degrees celcius, glass transition temperature." at 130.2,2119 h45
  text "5. TD > 350 degrees celcius, thermal decomposition." at 130.2,2044 h45
  text "6. Er = 4.0 +/- 5% @ 2.5GHz." at 130.2,1969 h45
  text "7. Minimum flammability rating UL94V-0, maximum dissipation factor 0.025." at 130.2,1894 h45
  text "8. Adjust prepreg for 0.062\", +/- 0.003\" finished thickness measured over soldermask." at 130.2,1819 h45
  text "9. Copper thickness 0.0014\", (1 oz)." at 130.2,1744 h45
  text "10. Hole size tolerance = +/- 0.003\" unless noted otherwise." at 130.2,1669 h45
  text "11. Hole centers and pad centers to be concentric within 0.002\"." at 130.2,1594 h45
  text "12. Drill chart dimensions are drill sizes and not finished hole sizes." at 130.2,1519 h45
  text "13. Finish - immersion gold over nickel.  No exposed bare copper permitted." at 130.2,1444 h45
  text "14. Thieving not allowed on layer 1." at 130.2,1369 h45
  text "15. Solder mask over bare copper, LPI class 2 gen. industrial registration +/- 0.004\"." at 130.2,1294 h45
  text "16. No coverage on solder pads permitted." at 130.2,1219 h45
  text "17. Refer to soldermask gerbers for tenting of vias." at 130.2,1144 h45
  text "18. White silkscreen legend over red soldermask - both sides." at 130.2,1069 h45
  text "19. Manufacturer icons not permitted on the silkscreen top layer." at 130.2,994 h45
  text "20. PCB serialization/panel placement ID on silkscreen bottom." at 130.2,919 h45
  text "21. Full electrical test against IPC-356A netlist." at 130.2,844 h45
  text "Layer" at 3190.48,-66.52 h60
  text "Name" at 3600.39,-66.52 h60
  text "Material" at 4530.14,-66.52 h60
  text "Thickness" at 5389.9,-66.52 h60
  text "Constant" at 6039.74,-66.52 h60
  text "Board Layer Stack" at 6609.6,-66.52 h60
  text "1" at 3190.48,-186.52 h60
  text "Top Paste" at 3600.39,-186.52 h60
  text "2" at 3190.48,-306.52 h60
  text "Top Overlay" at 3600.39,-306.52 h60
  text "3" at 3190.48,-426.52 h60
  text "Top Solder" at 3600.39,-426.52 h60
  text "Solder Resist" at 4530.14,-426.52 h60
  text "0.40mil" at 5389.9,-426.52 h60
  text "3.5" at 6039.74,-426.52 h60
  text "4" at 3190.48,-546.52 h60
  text "Top Layer" at 3600.39,-546.52 h60
  text "Copper" at 4530.14,-546.52 h60
  text "1.40mil" at 5389.9,-546.52 h60
  text "5" at 3190.48,-666.52 h60
  text "Dielectric1" at 3600.39,-666.52 h60
  text "HR370" at 4530.14,-666.52 h60
  text "16.00mil" at 5389.9,-666.52 h60
  text "4" at 6039.74,-666.52 h60
  text "6" at 3190.48,-786.52 h60
  text "Gnd Layer 2" at 3600.39,-786.52 h60
  text "Copper" at 4530.14,-786.52 h60
  text "1.40mil" at 5389.9,-786.52 h60
  text "7" at 3190.48,-906.52 h60
  text "Dielectric2" at 3600.39,-906.52 h60
  text "HR370" at 4530.14,-906.52 h60
  text "24.00mil" at 5389.9,-906.52 h60
  text "4" at 6039.74,-906.52 h60
  text "8" at 3190.48,-1026.52 h60
  text "Power Layer 3" at 3600.39,-1026.52 h60
  text "Copper" at 4530.14,-1026.52 h60
  text "1.40mil" at 5389.9,-1026.52 h60
  text "9" at 3190.48,-1146.52 h60
  text "Dielectric3" at 3600.39,-1146.52 h60
  text "HR370" at 4530.14,-1146.52 h60
  text "16.00mil" at 5389.9,-1146.52 h60
  text "4" at 6039.74,-1146.52 h60
  text "10" at 3190.48,-1266.52 h60
  text "Bottom Layer" at 3600.39,-1266.52 h60
  text "Copper" at 4530.14,-1266.52 h60
  text "1.40mil" at 5389.9,-1266.52 h60
  text "11" at 3190.48,-1386.52 h60
  text "Bottom Solder" at 3600.39,-1386.52 h60
  text "Solder Resist" at 4530.14,-1386.52 h60
  text "0.40mil" at 5389.9,-1386.52 h60
  text "3.5" at 6039.74,-1386.52 h60
  text "12" at 3190.48,-1506.52 h60
  text "Bottom Overlay" at 3600.39,-1506.52 h60
  text "13" at 3190.48,-1626.52 h60
  text "Bottom Paste" at 3600.39,-1626.52 h60
  text ".Legend" at -59,-3402 h60
  text ".Layer_Name" at 5814.2,-4299.1 h70

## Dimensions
2000,-1729 to 2000,0 on Drill Drawing
2000,-1729 to 0,-1729 on Drill Drawing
